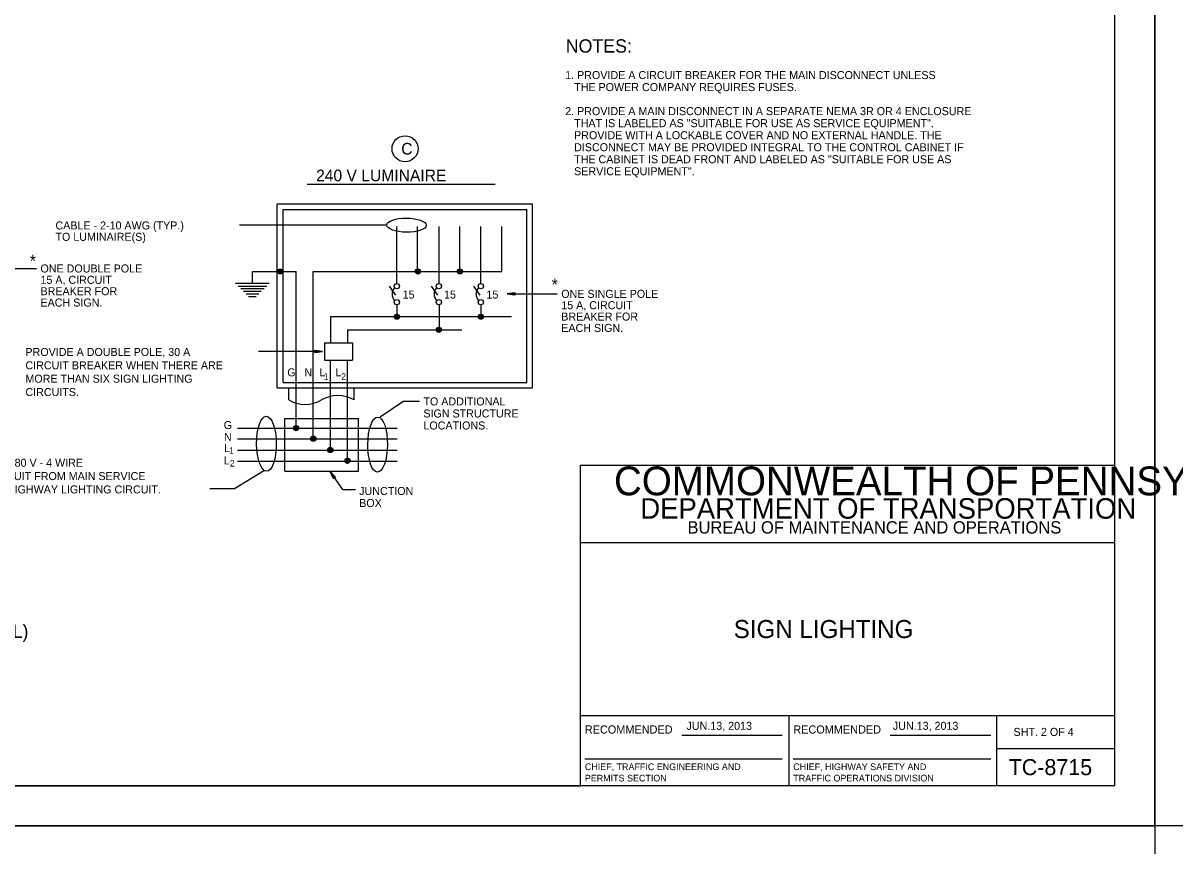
# Model space of a CAD drawing. Extents: x 36 to 2622, y -5330 to 219.
# Drawn here: x 1294.3 to 1725.4, y -4743.3 to -4435.3 of the extents above; entities that cross this region are included whole.
import ezdxf

# ---------------------------------------------------------------- set-up
doc = ezdxf.new("R2010")
doc.units = 0
for name, color, linetype in [('1', 7, 'Continuous'), ('2', 7, 'Continuous'), ('3', 7, 'Continuous'), ('PLT-BNDY', 7, 'Continuous')]:
    doc.layers.add(name, color=color, linetype=linetype)

# ---------------------------------------------------------------- blocks, each defined once
blk = doc.blocks.new('RARROW')
at = {"layer": '3'}
blk.add_lwpolyline([(-2.2695, 0.285), (-2.184875, 0.12075), (0, 0), (-2.2695, 0.285), (-2.38575, 0.384625), (0, 0), (-2.183125, -0.108), (-2.262875, -0.2705), (0, 0), (-2.38575, -0.379125), (-2.262875, -0.2705)], dxfattribs=at)

msp = doc.modelspace()

# ---------------------------------------------------------------- linework, layer by layer
at = {"layer": '1'}
for p, q in [((1702.86, -4720.83), (1702.86, -4156.83)), ((1502.86, -4720.83), (1502.86, -4600.83)), ((1502.86, -4600.83), (1702.86, -4600.83)), ((1702.86, -4629.83), (1502.86, -4629.83)), ((1502.86, -4694.45), (1702.86, -4694.45)), ((1580.86, -4694.45), (1580.86, -4720.83)), ((1658.73, -4720.83), (1658.73, -4694.45)), ((1540.79, -4701.88), (1578.41, -4701.88)), ((1618.79, -4701.88), (1656.41, -4701.88)), ((1504.54, -4710.78), (1578.41, -4710.78)), ((1582.54, -4710.78), (1656.41, -4710.78)), ((1658.73, -4706.83), (1702.86, -4706.83)), ((1702.86, -4720.83), (916.86, -4720.83)), ((916.86, -4720.83), (1502.86, -4720.83))]:
    msp.add_line(p, q, dxfattribs=at)
at = {"layer": '2'}
for p, q in [((1400.61, -4495.7), (1470.98, -4495.7)), ((1389.48, -4571.83), (1389.48, -4502.95)), ((1389.48, -4502.95), (1484.98, -4502.95)), ((1484.98, -4571.83), (1484.98, -4502.95)), ((1391.61, -4569.83), (1391.61, -4505.08)), ((1391.61, -4505.08), (1482.86, -4505.08)), ((1482.86, -4569.83), (1482.86, -4505.08)), ((1375.36, -4510.83), (1430.48, -4510.83)), ((1434.23, -4532.83), (1434.23, -4511.45)), ((1441.98, -4528.33), (1441.98, -4511.45)), ((1449.98, -4532.83), (1449.98, -4511.45)), ((1457.73, -4528.33), (1457.73, -4511.45)), ((1465.61, -4532.83), (1465.61, -4511.45)), ((1473.48, -4528.33), (1473.48, -4511.45)), ((1280.61, -4527.2), (1299.36, -4527.2)), ((1380.23, -4528.33), (1396.53, -4528.33)), ((1380.23, -4532.83), (1380.23, -4528.33)), ((1396.53, -4586.95), (1396.53, -4528.33)), ((1402.93, -4528.33), (1473.48, -4528.33)), ((1402.93, -4591.01), (1402.93, -4528.33)), ((1386.48, -4532.83), (1373.86, -4532.83)), ((1385.61, -4533.95), (1374.86, -4533.95)), ((1433.86, -4537.2), (1431.48, -4533.83)), ((1449.48, -4537.2), (1447.23, -4533.83)), ((1465.36, -4537.2), (1462.98, -4533.83)), ((1384.61, -4534.83), (1375.86, -4534.83)), ((1383.48, -4535.83), (1376.86, -4535.83)), ((1382.61, -4536.83), (1377.86, -4536.83)), ((1381.61, -4537.83), (1378.73, -4537.83)), ((1475.48, -4536.7), (1494.23, -4536.7)), ((1434.23, -4540.7), (1434.23, -4545.2)), ((1449.98, -4540.7), (1449.98, -4550.2)), ((1465.61, -4540.7), (1465.61, -4545.2)), ((1409.33, -4545.2), (1409.33, -4555.08)), ((1409.33, -4545.2), (1477.11, -4545.2)), ((1415.73, -4550.2), (1415.73, -4555.08)), ((1415.73, -4550.2), (1458.48, -4550.2)), ((1407.15, -4555.08), (1417.63, -4555.08)), ((1407.15, -4555.08), (1407.15, -4561.58)), ((1417.63, -4555.08), (1417.63, -4561.58)), ((1405.23, -4558.33), (1382.48, -4558.33)), ((1407.15, -4561.58), (1417.63, -4561.58)), ((1409.33, -4595.23), (1409.33, -4561.58)), ((1415.73, -4599.27), (1415.73, -4561.58)), ((1389.48, -4571.83), (1484.98, -4571.83)), ((1391.61, -4569.83), (1482.86, -4569.83)), ((1393.76, -4576.33), (1393.76, -4571.83)), ((1418.23, -4576.33), (1418.23, -4571.83)), ((1427.9, -4582.75), (1436.43, -4576.96)), ((1442.74, -4576.96), (1436.43, -4576.96)), ((1392.29, -4583.33), (1419.86, -4583.33)), ((1392.29, -4603.09), (1392.29, -4583.33)), ((1419.86, -4603.09), (1419.86, -4583.33)), ((1374.57, -4586.95), (1434.36, -4586.95)), ((1374.57, -4591.01), (1434.36, -4591.01)), ((1374.57, -4595.23), (1434.36, -4595.23)), ((1384.62, -4602.84), (1373.49, -4609.63)), ((1374.57, -4599.27), (1434.36, -4599.27)), ((1392.29, -4603.09), (1419.86, -4603.09)), ((1413.98, -4609.97), (1409.23, -4603.22)), ((1373.49, -4609.63), (1364.23, -4609.63)), ((1413.98, -4609.97), (1418.73, -4609.97))]:
    msp.add_line(p, q, dxfattribs=at)
for centre, radius in [((1437.27, -4482.41), 4.87), ((1390.56, -4528.31), 0.976), ((1390.56, -4528.31), 0.907), ((1390.56, -4528.31), 0.838), ((1390.56, -4528.31), 0.768), ((1390.56, -4528.31), 0.699), ((1390.56, -4528.31), 0.63), ((1390.56, -4528.31), 0.56), ((1390.56, -4528.31), 0.491), ((1390.56, -4528.31), 0.422), ((1390.56, -4528.31), 0.352), ((1390.56, -4528.31), 0.283), ((1390.56, -4528.31), 0.214), ((1390.56, -4528.31), 0.144), ((1390.56, -4528.31), 0.0749), ((1442.06, -4528.3), 0.976), ((1442.06, -4528.3), 0.907), ((1442.06, -4528.3), 0.838), ((1442.06, -4528.3), 0.768), ((1442.06, -4528.3), 0.699), ((1442.06, -4528.3), 0.63), ((1442.06, -4528.3), 0.56), ((1442.06, -4528.3), 0.491), ((1442.06, -4528.3), 0.422), ((1442.06, -4528.3), 0.352), ((1442.06, -4528.3), 0.283), ((1442.06, -4528.3), 0.214), ((1442.06, -4528.3), 0.144), ((1442.06, -4528.3), 0.0749), ((1457.77, -4528.3), 0.976), ((1457.77, -4528.3), 0.907), ((1457.77, -4528.3), 0.838), ((1457.77, -4528.3), 0.768), ((1457.77, -4528.3), 0.699), ((1457.77, -4528.3), 0.63), ((1457.77, -4528.3), 0.56), ((1457.77, -4528.3), 0.491), ((1457.77, -4528.3), 0.422), ((1457.77, -4528.3), 0.352), ((1457.77, -4528.3), 0.283), ((1457.77, -4528.3), 0.214), ((1457.77, -4528.3), 0.144), ((1457.77, -4528.3), 0.0749), ((1434.2, -4533.82), 0.976), ((1449.92, -4533.82), 0.976), ((1465.63, -4533.82), 0.976), ((1434.2, -4539.81), 0.976), ((1449.92, -4539.81), 0.976), ((1465.63, -4539.81), 0.976), ((1434.2, -4545.27), 0.976), ((1434.2, -4545.27), 0.907), ((1434.2, -4545.27), 0.838), ((1434.2, -4545.27), 0.768), ((1434.2, -4545.27), 0.699), ((1434.2, -4545.27), 0.63), ((1434.2, -4545.27), 0.56), ((1434.2, -4545.27), 0.491), ((1434.2, -4545.27), 0.422), ((1434.2, -4545.27), 0.352), ((1434.2, -4545.27), 0.283), ((1434.2, -4545.27), 0.214), ((1434.2, -4545.27), 0.144), ((1434.2, -4545.27), 0.0749), ((1465.63, -4545.27), 0.976), ((1465.63, -4545.27), 0.907), ((1465.63, -4545.27), 0.838), ((1465.63, -4545.27), 0.768), ((1465.63, -4545.27), 0.699), ((1465.63, -4545.27), 0.63), ((1465.63, -4545.27), 0.56), ((1465.63, -4545.27), 0.491), ((1465.63, -4545.27), 0.422), ((1465.63, -4545.27), 0.352), ((1465.63, -4545.27), 0.283), ((1465.63, -4545.27), 0.214), ((1465.63, -4545.27), 0.144), ((1465.63, -4545.27), 0.0749), ((1449.91, -4550.16), 0.976), ((1449.91, -4550.16), 0.907), ((1449.91, -4550.16), 0.838), ((1449.91, -4550.16), 0.768), ((1449.91, -4550.16), 0.699), ((1449.91, -4550.16), 0.63), ((1449.91, -4550.16), 0.56), ((1449.91, -4550.16), 0.491), ((1449.91, -4550.16), 0.422), ((1449.91, -4550.16), 0.352), ((1449.91, -4550.16), 0.283), ((1449.91, -4550.16), 0.214), ((1449.91, -4550.16), 0.144), ((1449.91, -4550.16), 0.0749), ((1396.53, -4586.94), 0.976), ((1396.53, -4586.94), 0.907), ((1396.53, -4586.94), 0.838), ((1396.53, -4586.94), 0.768), ((1396.53, -4586.94), 0.699), ((1396.53, -4586.94), 0.63), ((1396.53, -4586.94), 0.56), ((1396.53, -4586.94), 0.491), ((1396.53, -4586.94), 0.422), ((1396.53, -4586.94), 0.352), ((1396.53, -4586.94), 0.283), ((1396.53, -4586.94), 0.214), ((1396.53, -4586.94), 0.144), ((1396.53, -4586.94), 0.0749), ((1402.95, -4590.89), 0.976), ((1402.95, -4590.89), 0.907), ((1402.95, -4590.89), 0.838), ((1402.95, -4590.89), 0.768), ((1402.95, -4590.89), 0.699), ((1402.95, -4590.89), 0.63), ((1402.95, -4590.89), 0.56), ((1402.95, -4590.89), 0.491), ((1402.95, -4590.89), 0.422), ((1402.95, -4590.89), 0.352), ((1402.95, -4590.89), 0.283), ((1402.95, -4590.89), 0.214), ((1402.95, -4590.89), 0.144), ((1402.95, -4590.89), 0.0749), ((1409.3, -4595.12), 0.976), ((1409.3, -4595.12), 0.907), ((1409.3, -4595.12), 0.838), ((1409.3, -4595.12), 0.768), ((1409.3, -4595.12), 0.699), ((1409.3, -4595.12), 0.63), ((1409.3, -4595.12), 0.56), ((1409.3, -4595.12), 0.491), ((1409.3, -4595.12), 0.422), ((1409.3, -4595.12), 0.352), ((1409.3, -4595.12), 0.283), ((1409.3, -4595.12), 0.214), ((1409.3, -4595.12), 0.144), ((1409.3, -4595.12), 0.0749), ((1415.73, -4599.17), 0.976), ((1415.73, -4599.17), 0.907), ((1415.73, -4599.17), 0.838), ((1415.73, -4599.17), 0.768), ((1415.73, -4599.17), 0.699), ((1415.73, -4599.17), 0.63), ((1415.73, -4599.17), 0.56), ((1415.73, -4599.17), 0.491), ((1415.73, -4599.17), 0.422), ((1415.73, -4599.17), 0.352), ((1415.73, -4599.17), 0.283), ((1415.73, -4599.17), 0.214), ((1415.73, -4599.17), 0.144), ((1415.73, -4599.17), 0.0749)]:
    msp.add_circle(centre, radius, dxfattribs=at)
for centre in [(1436.17, -4536.75), (1451.88, -4536.75), (1467.59, -4536.75)]:
    msp.add_arc(centre, 3.73, 139.9422, 220.6112, dxfattribs=at)
for centre, major_axis in [((1437.85, -4510.99), (-7.37, 0.05)), ((1385.41, -4592.8), (-0.07, 10.31)), ((1427.01, -4593.13), (0.07, 10.31))]:
    msp.add_ellipse(centre, major_axis=major_axis, ratio=0.356583, dxfattribs=at)
for centre, major_axis in [((1399.87, -4570.95), (9.55, 0)), ((1412.11, -4581.87), (-9.55, 0))]:
    msp.add_ellipse(centre, major_axis=major_axis, ratio=0.74367, start_param=4.017593, end_param=5.407185, dxfattribs=at)
at = {"layer": 'PLT-BNDY'}
for points in [[(876.86, -4141.83), (1717.86, -4141.83), (1717.86, -4735.83), (876.86, -4735.83)], [(1717.86, -4141.83), (2558.86, -4141.83), (2558.86, -4735.83), (1717.86, -4735.83)], [(876.86, -4735.83), (1717.86, -4735.83), (1717.86, -5329.83), (876.86, -5329.83)]]:
    msp.add_lwpolyline(points, close=True, dxfattribs=at)

# ---------------------------------------------------------------- block references
at = {"layer": '2', "xscale": 1.2574347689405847}
for p, yscale, rotation in [((1475.48, -4536.7), 1.3092961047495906, 180), ((1409.23, -4603.22), 1.3092961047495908, 124.9953898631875)]:
    msp.add_blockref('RARROW', p, dxfattribs=dict(at, yscale=yscale, rotation=rotation))
at = {"layer": '2', "xscale": 1.2574347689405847, "yscale": 1.3092961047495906}
msp.add_blockref('RARROW', (1406.33, -4558.33), dxfattribs=at)

# ---------------------------------------------------------------- texts
at = {"layer": '1'}
for s, height, p in [('COMMONWEALTH OF PENNSYLVANIA', 10.7828, (1515.45, -4612.1)), ('DEPARTMENT OF TRANSPORTATION', 7.6837, (1525.31, -4620.85)), ('BUREAU OF MAINTENANCE AND OPERATIONS', 4.6253, (1542.95, -4626.41)), ('SIGN LIGHTING', 6.75, (1560.26, -4665.52)), ('RECOMMENDED', 3.048, (1504.54, -4701.26)), ('RECOMMENDED', 3.048, (1582.54, -4701.26)), ('SHT. 2 OF 4', 3, (1664.94, -4702.14)), ('TC-8715', 6, (1663.14, -4716.83)), ('CHIEF, TRAFFIC ENGINEERING AND', 2.5, (1504.54, -4714.94)), ('CHIEF, HIGHWAY SAFETY AND', 2.5, (1582.54, -4714.94)), ('PERMITS SECTION', 2.5, (1504.54, -4719.19)), ('TRAFFIC OPERATIONS DIVISION', 2.5, (1582.54, -4719.19))]:
    msp.add_text(s, height=height, dxfattribs=at).set_placement(p)
at = {"layer": '2'}
for s, height, p in [('NOTES:', 4.972, (1497.4, -4446.41)), ('1. PROVIDE A CIRCUIT BREAKER FOR THE MAIN DISCONNECT UNLESS', 3, (1497.18, -4456.32)), ('   THE POWER COMPANY REQUIRES FUSES.', 3, (1497.18, -4460.82)), ('2. PROVIDE A MAIN DISCONNECT IN A SEPARATE NEMA 3R OR 4 ENCLOSURE', 3, (1497.18, -4469.82)), ('   THAT IS LABELED AS "SUITABLE FOR USE AS SERVICE EQUIPMENT". ', 3, (1497.18, -4474.32)), ('   PROVIDE WITH A LOCKABLE COVER AND NO EXTERNAL HANDLE. THE', 3, (1497.18, -4478.82)), ('C', 4.37, (1435.86, -4484.58)), ('   DISCONNECT MAY BE PROVIDED INTEGRAL TO THE CONTROL CABINET IF', 3, (1497.18, -4483.32)), ('   THE CABINET IS DEAD FRONT AND LABELED AS "SUITABLE FOR USE AS', 3, (1497.18, -4487.82)), ('240 V LUMINAIRE', 4.3747, (1403.98, -4494.58)), ('   SERVICE EQUIPMENT".', 3, (1497.18, -4492.32)), ('CABLE - 2-10 AWG (TYP.)', 2.9955, (1306.46, -4512.6)), ('TO LUMINAIRE(S)', 2.9955, (1306.46, -4516.85)), ('*', 4.49, (1296.86, -4526.58)), ('ONE DOUBLE POLE', 2.9955, (1300.86, -4528.7)), ('15 A, CIRCUIT', 2.9955, (1300.86, -4532.95)), ('BREAKER FOR', 2.9955, (1300.86, -4537.2)), ('*', 4.49, (1492.11, -4535.45)), ('EACH SIGN.', 2.996, (1300.86, -4541.45)), ('15', 2.996, (1436.36, -4538.45)), ('15', 2.996, (1451.86, -4538.45)), ('15', 2.996, (1467.73, -4538.45)), ('ONE SINGLE POLE', 2.9955, (1495.73, -4538.2)), ('15 A, CIRCUIT', 2.9955, (1495.73, -4542.45)), ('BREAKER FOR', 2.9955, (1495.73, -4546.7)), ('EACH SIGN.', 2.996, (1495.73, -4550.95)), ('PROVIDE A DOUBLE POLE, 30 A', 2.9955, (1295.23, -4559.95)), ('CIRCUIT BREAKER WHEN THERE ARE', 2.9955, (1295.23, -4564.95)), ('MORE THAN SIX SIGN LIGHTING', 2.9955, (1295.23, -4569.95)), ('G', 3, (1393.2, -4567.58)), ('N', 3, (1399.61, -4567.58)), ('L', 3, (1405.21, -4567.58)), ('1', 2.43, (1406.83, -4568.83)), ('L', 3, (1411.23, -4567.58)), ('2', 2.43, (1413.36, -4568.83)), ('CIRCUITS.', 2.996, (1295.23, -4574.95)), ('TO ADDITIONAL', 2.9955, (1444.14, -4578.46)), ('SIGN STRUCTURE', 2.9955, (1444.14, -4582.96)), ('LOCATIONS.', 2.996, (1444.14, -4587.46)), ('N', 3, (1369.51, -4591.72)), ('L', 3, (1369.51, -4595.94)), ('1', 2.43, (1371.41, -4596.55)), ('240/480 V - 4 WIRE', 2.9955, (1281.16, -4601.4)), ('L', 3, (1369.47, -4600.53)), ('2', 2.43, (1371.69, -4601.32)), ('CIRCUIT FROM MAIN SERVICE', 2.9955, (1281.16, -4606.4)), ('OR HIGHWAY LIGHTING CIRCUIT.', 2.9955, (1281.16, -4611.39)), ('JUNCTION', 2.996, (1420.11, -4611.97)), ('BOX', 2.996, (1420.11, -4616.47)), ('SIGN STRUCTURE DISCONNECT (TYPICAL)', 5, (1156.67, -4665.49)), ('JUN.13, 2013', 2.9955, (1542.59, -4699.86)), ('JUN.13, 2013', 2.9955, (1619.81, -4699.86))]:
    msp.add_text(s, height=height, dxfattribs=at).set_placement(p)
msp.add_text('G', height=3, rotation=360, dxfattribs=at).set_placement((1369.43, -4587.31))

doc.saveas('drawing.dxf')
